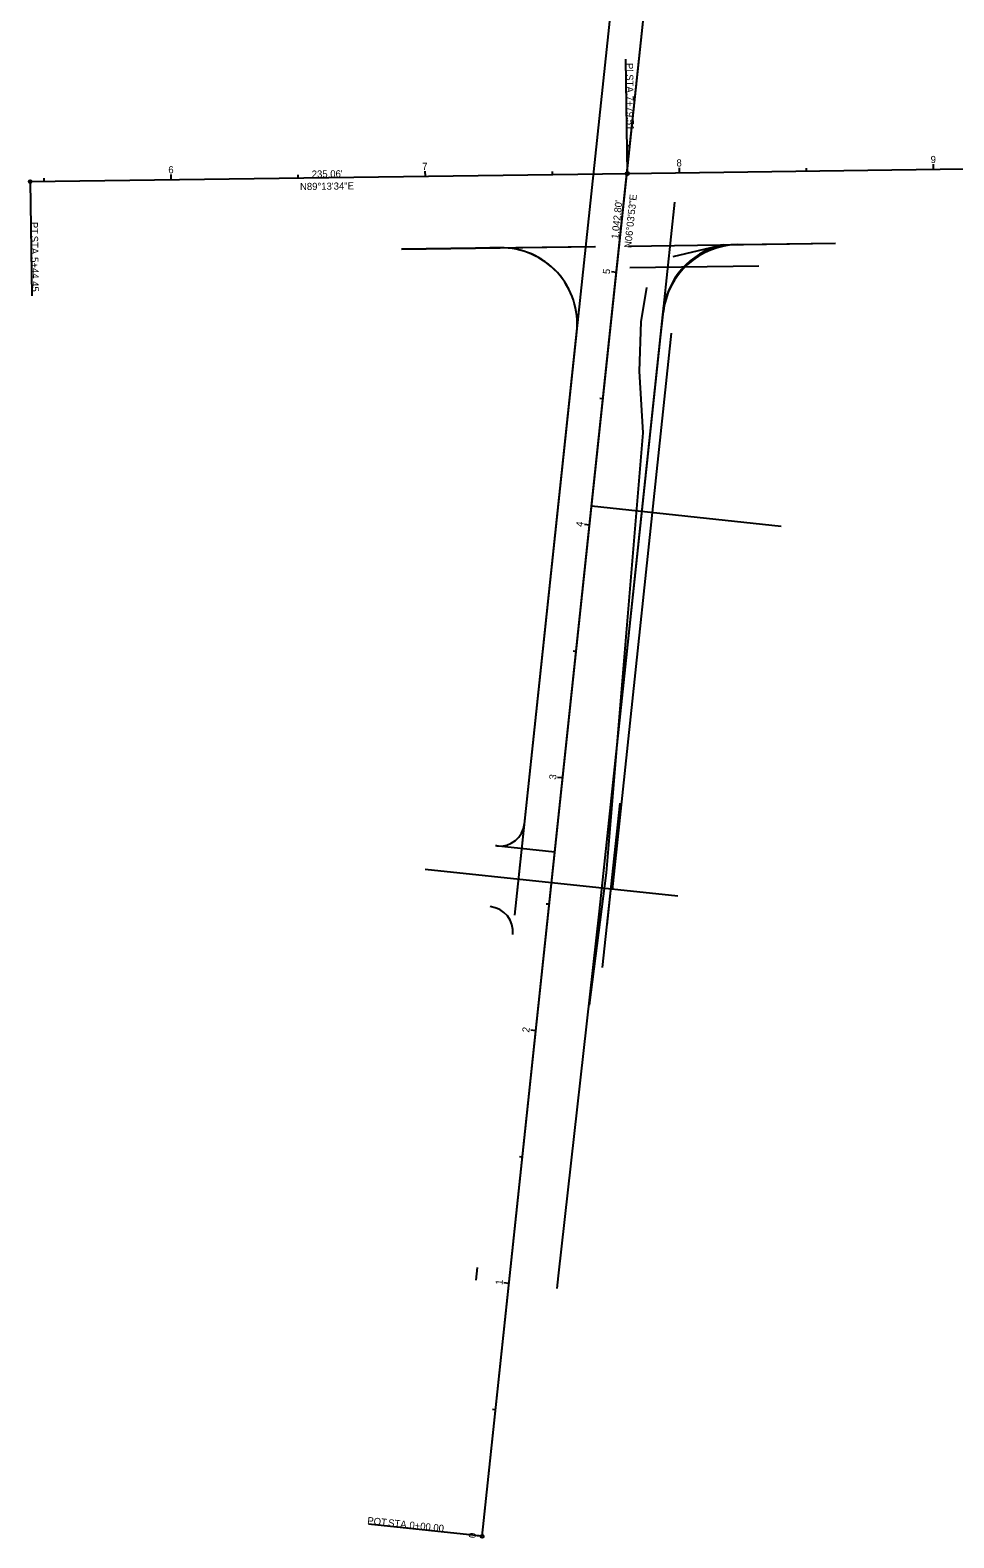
# Model space of a CAD drawing. Extents: x 1369241 to 1370511, y 405374 to 406419.
# Drawn here: x 1369789 to 1370152, y 405374 to 405967 of the extents above; entities that cross this region are included whole.
import ezdxf

# ---------------------------------------------------------------- set-up
doc = ezdxf.new("R2010")
doc.units = 0
for name, color, linetype in [('DT_P_Contour_Major', 7, 'Continuous'), ('DT_P_Spot_Elevations', 7, 'Continuous'), ('GE_P_Alignment_100_Bearings', 7, 'Continuous'), ('GE_P_Alignment_100_Cardinal_Points', 7, 'Continuous'), ('GE_P_Alignment_100_Distances', 7, 'Continuous'), ('GE_P_Alignment_100_Stations', 7, 'Continuous'), ('GE_P_Driveway_CL', 7, 'Continuous'), ('PV_P_EOP', 7, 'Continuous'), ('RW_X_CL', 7, 'Continuous'), ('SC_Scratch10', 7, 'Continuous'), ('SG_P_Mast_Arm', 7, 'Continuous'), ('SG_P_Poles', 7, 'Continuous')]:
    doc.layers.add(name, color=color, linetype=linetype)

msp = doc.modelspace()

# ---------------------------------------------------------------- linework, layer by layer
at = {"layer": 'DT_P_Contour_Major'}
for p, q in [((1370003.71, 405848.05), (1370063.7, 406412.63)), ((1370036.53, 405844.56), (1370042.33, 405899.18)), ((1369969.48, 405881.16), (1370010.53, 405881.72)), ((1369969.48, 405881.16), (1369973.47, 405881.22)), ((1369973.47, 405881.22), (1369969.48, 405881.16)), ((1370061.47, 405882.4), (1370041.53, 405877.63)), ((1370061.47, 405882.4), (1370060.61, 405882.2)), ((1370060.61, 405882.2), (1370061.47, 405882.4)), ((1370036.53, 405844.56), (1370037.76, 405856.19)), ((1370036.53, 405844.56), (1370037.76, 405856.19)), ((1370003.71, 405848.05), (1370003.71, 405848.05)), ((1370003.71, 405848.05), (1370003.71, 405848.05))]:
    msp.add_line(p, q, dxfattribs=at)
for centre, start, end in [((1369973.88, 405851.22), 353.93523, 90.77388), ((1369973.88, 405851.22), 353.93523, 90.77388), ((1370067.59, 405853.02), 103.45067, 173.93523), ((1370067.59, 405853.02), 103.45067, 173.93523)]:
    msp.add_arc(centre, 30, start, end, dxfattribs=at)
at = {"layer": 'DT_P_Spot_Elevations'}
for p, q in [((1370013.86, 405598.09), (1370020.72, 405662.63)), ((1369995.04, 405643.42), (1369971.67, 405645.9)), ((1369972.17, 405645.85), (1369971.67, 405645.9)), ((1370015.62, 405614.68), (1370018.66, 405643.32))]:
    msp.add_line(p, q, dxfattribs=at)
for centre, start, end in [((1369973.23, 405655.79), 263.93523, 353.93523), ((1369968.58, 405612.04), 353.93523, 83.93523)]:
    msp.add_arc(centre, 10, start, end, dxfattribs=at)
at = {"layer": 'GE_P_Alignment_100_Cardinal_Points'}
for p, q in [((1370023.59, 405910.4), (1370022.99, 405955.39)), ((1369788.56, 405907.22), (1369789.17, 405862.23)), ((1369966.45, 405374.29), (1369921.7, 405379.04))]:
    msp.add_line(p, q, dxfattribs=at)
for centre in [(1369788.56, 405907.22), (1370023.59, 405910.4), (1369966.45, 405374.29)]:
    msp.add_circle(centre, 0.6, dxfattribs=at)
at = {"layer": 'GE_P_Alignment_100_Stations'}
for p, q in [((1370024.56, 405921.21), (1370023.36, 405921.34)), ((1370144.08, 405912.02), (1370144.05, 405914.02)), ((1369794.11, 405907.3), (1369794.09, 405908.5)), ((1369844.11, 405907.97), (1369844.08, 405909.97)), ((1369894.1, 405908.65), (1369894.08, 405909.85)), ((1369944.1, 405909.32), (1369944.07, 405911.32)), ((1369994.09, 405910), (1369994.08, 405911.2)), ((1370044.09, 405910.67), (1370044.06, 405912.67)), ((1370094.08, 405911.34), (1370094.07, 405912.54)), ((1370019.27, 405871.49), (1370017.29, 405871.7)), ((1370013.99, 405821.77), (1370012.8, 405821.9)), ((1370008.71, 405772.05), (1370006.72, 405772.26)), ((1370003.43, 405722.33), (1370002.23, 405722.45)), ((1369998.14, 405672.61), (1369996.15, 405672.82)), ((1369992.86, 405622.89), (1369991.67, 405623.01)), ((1369987.58, 405573.17), (1369985.59, 405573.38)), ((1369982.3, 405523.45), (1369981.1, 405523.57)), ((1369977.01, 405473.73), (1369975.02, 405473.94)), ((1369971.73, 405424.01), (1369970.54, 405424.13)), ((1369966.45, 405374.29), (1369964.46, 405374.5))]:
    msp.add_line(p, q, dxfattribs=at)
at = {"layer": 'GE_P_Driveway_CL'}
for p, q in [((1370009.51, 405779.63), (1370084.09, 405771.71)), ((1369944.05, 405636.77), (1369993.77, 405631.49)), ((1369993.77, 405631.49), (1370043.49, 405626.2))]:
    msp.add_line(p, q, dxfattribs=at)
at = {"layer": 'PV_P_EOP'}
msp.add_line((1369972.17, 405645.85), (1369971.67, 405645.9), dxfattribs=at)
msp.add_arc((1369973.23, 405655.79), 10, 263.93523, 353.93523, dxfattribs=at)
at = {"layer": 'RW_X_CL'}
for p, q in [((1370023.41, 405910.39), (1370075.13, 406396.09)), ((1369966.45, 405374.29), (1370023.41, 405910.39))]:
    msp.add_line(p, q, dxfattribs=at)
at = {"layer": 'SC_Scratch10'}
msp.add_line((1370040.87, 405847.64), (1370017.6, 405628.61), dxfattribs=at)
at = {"layer": 'SG_P_Mast_Arm'}
for p, q in [((1369934.64, 405880.65), (1370011.11, 405881.68)), ((1369934.64, 405880.65), (1369973.47, 405881.18)), ((1369973.47, 405881.18), (1369934.64, 405880.65)), ((1369973.47, 405881.18), (1369934.64, 405880.65)), ((1370024.06, 405881.87), (1370105.52, 405882.97)), ((1370067.13, 405882.45), (1370105.52, 405882.97)), ((1370067.13, 405882.45), (1370105.52, 405882.97)), ((1370024.57, 405873.41), (1370075.34, 405874.09)), ((1370029.02, 405852.07), (1370031.28, 405865.55)), ((1369979.34, 405618.69), (1370004.66, 405856.97)), ((1370012.69, 405620.18), (1370038, 405858.48)), ((1370012.69, 405620.18), (1370037.7, 405855.62)), ((1370012.69, 405620.18), (1370037.7, 405855.62)), ((1370028.37, 405832.65), (1370029.02, 405852.07)), ((1369979.34, 405618.69), (1370003.71, 405848.01)), ((1369979.34, 405618.69), (1370003.71, 405848.01)), ((1369979.34, 405618.69), (1370003.71, 405848.01)), ((1370029.81, 405808.41), (1370028.37, 405832.65)), ((1370015.33, 405635.31), (1370029.81, 405808.41)), ((1370008.66, 405583.22), (1370015.33, 405635.31)), ((1369996.43, 405476.69), (1370012.69, 405620.18)), ((1369964.08, 405475.09), (1369964.61, 405480.08)), ((1369964.08, 405475.09), (1369964.61, 405480.08)), ((1369964.08, 405475.09), (1369964.61, 405480.08)), ((1369995.91, 405471.71), (1369996.43, 405476.69)), ((1369995.91, 405471.71), (1369996.43, 405476.69))]:
    msp.add_line(p, q, dxfattribs=at)
for centre, start, end in [((1369973.87, 405851.18), 353.93523, 90.77388), ((1369973.87, 405851.18), 353.93523, 90.77388), ((1369973.87, 405851.18), 353.93523, 90.77388), ((1370067.53, 405852.45), 90.77029, 173.93523), ((1370067.53, 405852.45), 90.77029, 173.93523)]:
    msp.add_arc(centre, 30, start, end, dxfattribs=at)
at = {"layer": 'SG_P_Poles'}
for p, q in [((1369966.45, 405374.29), (1370076.62, 406411.25)), ((1370023.59, 405910.4), (1370508.58, 405916.92)), ((1369788.56, 405907.22), (1370023.59, 405910.4)), ((1369788.56, 405907.22), (1370023.59, 405910.4))]:
    msp.add_line(p, q, dxfattribs=at)

# ---------------------------------------------------------------- texts
at = {"layer": 'GE_P_Alignment_100_Bearings'}
for s, rotation, p in [('N89°13\'34"E', 0.77388, (1369894.78, 405903.86)), ('N06°03\'53"E', 83.93523, (1370025.11, 405880.96))]:
    msp.add_text(s, height=2.8, rotation=rotation, dxfattribs=at).set_placement(p)
at = {"layer": 'GE_P_Alignment_100_Cardinal_Points'}
for s, rotation, p in [('PI', 270.77029, (1370023.05, 405953.86)), (' STA. ', 270.77029, (1370023.1, 405950.47)), ('7+79.51', 270.77029, (1370023.23, 405941.01)), ('PT', 270.77388, (1369788.81, 405891.35)), (' STA. ', 270.77388, (1369788.87, 405886.94)), ('5+44.45', 270.77388, (1369789, 405877.49)), ('POT', 353.93523, (1369921.14, 405379.14)), (' STA. ', 353.93523, (1369928.3, 405378.38)), ('0+00.00', 353.93523, (1369937.7, 405377.38))]:
    msp.add_text(s, height=2.8, rotation=rotation, dxfattribs=at).set_placement(p)
at = {"layer": 'GE_P_Alignment_100_Distances'}
for s, rotation, p in [("235.06'", 0.77388, (1369899.4, 405908.76)), ("1,042.80'", 83.93523, (1370020.03, 405884.54))]:
    msp.add_text(s, height=2.8, rotation=rotation, dxfattribs=at).set_placement(p)
at = {"layer": 'GE_P_Alignment_100_Stations'}
for s, rotation, p in [('6', 0.77388, (1369842.95, 405910.46)), ('7', 0.77388, (1369942.88, 405911.81)), ('8', 0.77029, (1370042.95, 405913.16)), ('9', 0.77029, (1370142.96, 405914.5)), ('5', 83.93523, (1370016.67, 405870.69)), ('4', 83.93523, (1370006.11, 405771.28)), ('3', 83.93523, (1369995.55, 405671.84)), ('2', 83.93523, (1369984.98, 405572.39)), ('1', 83.93523, (1369974.43, 405473.08)), ('0', 83.93523, (1369963.84, 405373.45))]:
    msp.add_text(s, height=2.8, rotation=rotation, dxfattribs=at).set_placement(p)

doc.saveas('drawing.dxf')
